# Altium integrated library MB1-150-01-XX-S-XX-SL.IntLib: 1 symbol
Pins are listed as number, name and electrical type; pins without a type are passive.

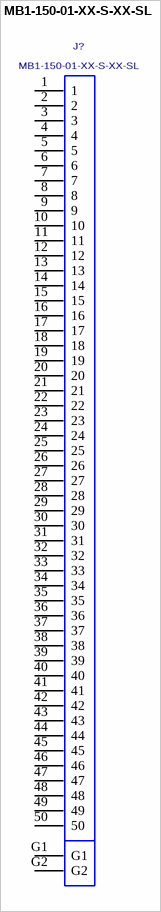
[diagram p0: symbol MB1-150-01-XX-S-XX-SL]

## MB1-150-01-XX-S-XX-SL
designator J?
1mm MINI-CARD GUIDE; MANUFACTURER: SAMTEC
footprint MB1-150-01-XX-S-XX-SL
pins: 1, 2, 3, 4, 5, 6, 7, 8, 9, 10, 11, 12, 13, 14, 15, 16, 17, 18, 19, 20, 21, 22, 23, 24, 25, 26, 27, 28, 29, 30, 31, 32, 33, 34, 35, 36, 37, 38, 39, 40, 41, 42, 43, 44, 45, 46, 47, 48, 49, 50, G1, G2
